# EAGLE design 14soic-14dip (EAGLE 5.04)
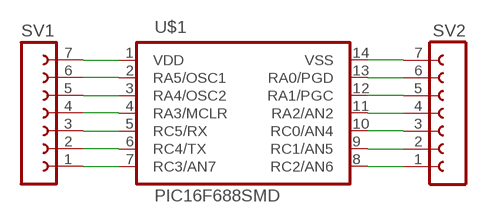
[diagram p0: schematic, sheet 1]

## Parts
SV1  FE07-1  [FE07]
SV2  FE07-1  [FE07]
U$1  PIC16F688SMD  [SOIC-14]

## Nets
N$1: SV1.1 U$1.7(RC3/AN7)
N$2: SV1.2 U$1.6(RC4/TX)
N$3: SV1.3 U$1.5(RC5/RX)
N$4: SV1.4 U$1.4(RA3/MCLR)
N$5: SV1.5 U$1.3(RA4/OSC2)
N$6: SV1.6 U$1.2(RA5/OSC1)
N$7: SV1.7 U$1.1(VDD)
N$8: SV2.1 U$1.8(RC2/AN6)
N$9: SV2.2 U$1.9(RC1/AN5)
N$10: SV2.3 U$1.10(RC0/AN4)
N$11: SV2.4 U$1.11(RA2/AN2)
N$12: SV2.5 U$1.12(RA1/PGC)
N$13: SV2.6 U$1.13(RA0/PGD)
N$14: SV2.7 U$1.14(VSS)

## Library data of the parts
SV1 SV2 = con-lsta:FE07-1: FEMALE HEADER
U$1 = SparkFun:PIC16F688: PIC 16F688 8-Bit PIC16F88

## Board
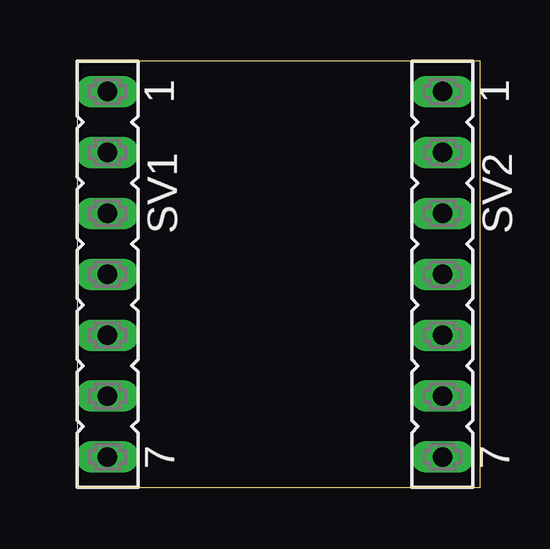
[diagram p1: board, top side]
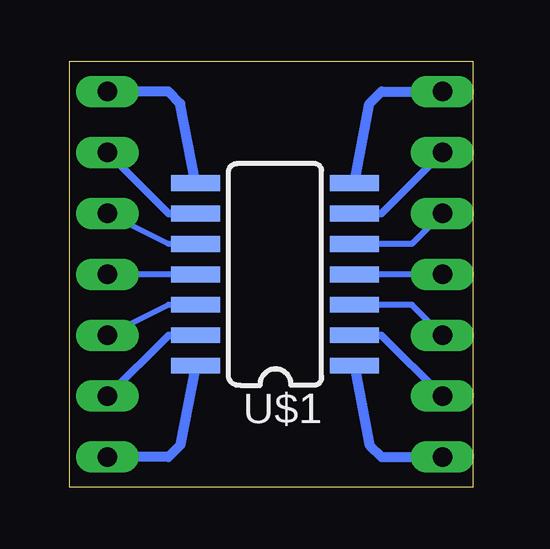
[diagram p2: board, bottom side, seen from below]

Size 16.82 x 17.77 mm. Coordinates in mm from the lower left corner, seen from the top.
Outline: 0,0 16.82,0 16.82,17.77 0,17.77 0,0
Copper layers (1*16): Top 0.035mm / dielectric 1.5mm / Bottom 0.035mm
Design rules "default": minimum track width 10mil, minimum drill 24mil, track to track 8mil, track to pad 8mil, pad to pad 8mil, via to via 8mil, smd to smd 8mil, copper to edge 40mil, drill to drill 8mil, minimum pad ring 10mil, minimum via ring 8mil, stop-mask expansion 4mil, vias tented up to drill 0mil, thermal gap 10mil

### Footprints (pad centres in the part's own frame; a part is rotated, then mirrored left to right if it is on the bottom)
FE07 = drill 0.813 long: 1 -7.62,0; 2 -5.08,0; 3 -2.54,0; 4 0,0; 5 2.54,0; 6 5.08,0; 7 7.62,0
SOIC-14 = smd 0.66 x 2.032: 1 -4.445,-3.315; 2 -3.175,-3.315; 3 -1.905,-3.315; 4 -0.635,-3.315; 5 0.635,-3.315; 6 1.905,-3.315; 7 3.175,-3.315; 8 3.175,3.315; 9 1.905,3.315; 10 0.635,3.315; 11 -0.635,3.315; 12 -1.905,3.315; 13 -3.175,3.315; 14 -4.445,3.315

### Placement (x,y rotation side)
SV1  1.27,8.89 270 top
SV2  15.24,8.89 270 top
U$1  8.26,9.53 90 bottom

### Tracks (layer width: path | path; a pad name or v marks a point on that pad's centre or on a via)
N$1
  Bottom 0.406: U$1.7 4.3,16.02 3.81,16.51 SV1.1
N$2
  Bottom 0.305: U$1.6 3.81,11.43 SV1.2
N$3
  Bottom 0.254: SV1.3 2.54,10.16 3.81,10.16 U$1.5
N$4
  Bottom 0.254: U$1.4 3.81,8.89 2.54,8.89 SV1.4
N$5
  Bottom 0.254: SV1.5 2.54,7.62 3.81,7.62 U$1.3
N$6
  Bottom 0.305: U$1.2 3.81,6.35 SV1.6
N$7
  Bottom 0.406: U$1.1 4.3,1.76 3.81,1.27 SV1.7
N$8
  Bottom 0.406: U$1.8 12.21,16.02 12.7,16.51 SV2.1
N$9
  Bottom 0.305: SV2.2 12.7,11.43 U$1.9
N$10
  Bottom 0.254: SV2.3 12.7,10.16 11.43,10.16 U$1.10
N$11
  Bottom 0.254: U$1.11 11.43,8.89 12.7,8.89 SV2.4
N$12
  Bottom 0.254: SV2.5 12.7,7.62 11.43,7.62 U$1.12
N$13
  Bottom 0.305: SV2.6 12.7,6.35 U$1.13
N$14
  Bottom 0.406: U$1.14 12.21,1.76 12.7,1.27 SV2.7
